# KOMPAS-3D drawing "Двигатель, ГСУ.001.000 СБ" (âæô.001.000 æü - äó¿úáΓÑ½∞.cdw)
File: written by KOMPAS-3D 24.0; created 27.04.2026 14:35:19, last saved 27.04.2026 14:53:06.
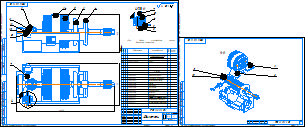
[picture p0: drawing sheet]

Document properties: Автор: User7; Форматы листов документа: A3, A2; Полное имя файла: ГСУ.001.000 СБ - Двигатель.a3d; Масса: 0.59734; Наименование: Двигатель; Количество листов документа: 2; Параметр неуказанной шероховатости: Ra 6,2

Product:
- Component [assembly]: Ротор  | designation ГСУ.001.100 СБ  | qty 1  | pos. 1  | Масса: 0.220757; source file: ГСУ.001.100 СБ - Ротор.a3d, ГСУ.001.100 СБ - Ротор.spw
- Component [detail]: Рама двигателя  | designation ГСУ.001.001  | qty 1  | pos. 4  | Масса: 0.218408; Автор: User7; source file: ГСУ.001.001 - Рама двигателя.m3d
- Component [detail]: Основание стартера  | designation ГСУ.001.002  | qty 2  | pos. 5  | Масса: 0.054294; Автор: User7; source file: ГСУ.001.002 - Основание стартера.m3d
- Component [detail]: Держатель щеток  | designation ГСУ.001.003  | qty 2  | pos. 6  | Масса: 0.006286; Автор: User7; source file: ГСУ.001.003 - Держатель щеток.m3d
- Component [detail]: Щетка  | designation ГСУ.001.004  | qty 2  | pos. 7  | Масса: 0.001131; Автор: User7; source file: ГСУ.001.004 - Щетка.m3d
- Component [detail]: Пластина  | designation ГСУ.001.005  | qty 2  | pos. 8  | Масса: 0.002713; Автор: User7; source file: ГСУ.001.005 - Пластина.m3d
- Component [detail]: Уплотнитель  | designation ГСУ.001.007  | qty 2  | pos. 10  | Масса: 0.000505; Автор: User7; source file: ГСУ.001.007 - Уплотнитель.m3d
- Component [detail]: Пружина  | designation ГСУ.001.008  | qty 2  | pos. 11  | Масса: 0.000147; Автор: User7; source file: ГСУ.001.008 - Пружина.m3d
- Component [detail]: Обмотка  | designation ГСУ.001.009  | qty 2  | pos. 12  | Масса: 0.009785; Автор: User7; source file: ГСУ.001.009 - Обмотка.m3d
- Component [detail]: Пластина держателя пружин  | designation ГСУ.001.011  | qty 2  | pos. 13  | Масса: 0.000005; Автор: User7; source file: ГСУ.001.011 - Пластина держателя пружин.m3d
- Component [detail]: Держатель стартера  | designation ГСУ.001.012  | qty 1  | pos. 14  | Масса: 0.003518; Автор: User7; source file: ГСУ.001.012 - Держатель стартера.m3d
- Component [detail]: Пластина держателя втулок ротора  | designation ГСУ.001.013  | qty 1  | pos. 15  | Масса: 0.000666; Автор: User7; source file: ГСУ.001.013 - Пластина держателя втулок ротора.m3d
- Component [detail]: Пластинка  | designation ГСУ.001.006  | qty 2  | pos. 9  | Масса: 0.002129; Автор: User7; source file: ГСУ.001.006 - Пластинка.m3d
- Part/product: Двигатель  | designation ГСУ.001.000 СБ
    Масса: 0.59734

Views: Выносной элемент 3, Выносной элемент А, Выносной элемент, Сечение проволоки, Сечение проволоки 2
Referenced files in C:\Users\User7\Desktop\Двигатель мясорубки\: ГСУ.001.000 СБ - Двигатель.a3d, ГСУ.001.100 СБ - Ротор.a3d, ГСУ.001.001 - Рама двигателя.m3d, ГСУ.001.002 - Основание стартера.m3d, ГСУ.001.003 - Держатель щеток.m3d, ГСУ.001.004 - Щетка.m3d, ГСУ.001.005 - Пластина.m3d, ГСУ.001.007 - Уплотнитель.m3d, ГСУ.001.008 - Пружина.m3d, ГСУ.001.009 - Обмотка.m3d, ГСУ.001.011 - Пластина держателя пружин.m3d, ГСУ.001.012 - Держатель стартера.m3d, ГСУ.001.013 - Пластина держателя втулок ротора.m3d, ГСУ.001.006 - Пластинка.m3d, ГСУ.001.000 СБ - Двигатель.cdw, ГСУ.001.101 - Звездочка.m3d, ГСУ.001.102 - Вал ротора.m3d, ГСУ.001.103 - Шестеренка.m3d, ГСУ.001.104 - Пропеллер.m3d, ГСУ.001.105 - Коллектор.m3d, ГСУ.001.106 - Шайба.m3d, ГСУ.001.107 - Втулка.m3d, ГСУ.001.108 - Пластина.m3d
Referenced files in C:\Program Files\ASCON\KOMPAS-3D v21\Libs\PARTLib\DATA\vault\Methods\Kompas\3D\: PLib_Nut_OST92_900.m3d
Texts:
  key
  prop
  position
  ГСУ.001.000 СБ
  Ra 6,2
  Ra 6,2 ( )
  Программные изделия  и базы данных
  Принадлежности
  Приспособления
  Упаковка
  ГСУ.001.100 СБ
  Ротор
  ГСУ.001.001
  Рама двигателя
  ГСУ.001.002
  Основание стартера
  ГСУ.001.003
  Держатель щеток
  ГСУ.001.004
  Щетка
  ГСУ.001.005
  Пластина
  ГСУ.001.007
  Уплотнитель
  ГСУ.001.008
  Пружина
  ГСУ.001.009
  Обмотка
  ГСУ.001.011
  Пластина держателя пружин
  ГСУ.001.012
  Держатель стартера
  ГСУ.001.013
  Пластина держателя втулок ротора
  ГСУ.001.006
  Пластинка
  Двигатель
  Звездочка
  ГСУ.001.101
  ГСУ.001.101 Звездочка
  Вал ротора
  ГСУ.001.102
  ГСУ.001.102 Вал ротора
  Шестеренка
  ГСУ.001.103
  ГСУ.001.103 Шестеренка
  Пропеллер
  ГСУ.001.104
  ГСУ.001.104 Пропеллер
  Коллектор
  ГСУ.001.105
  ГСУ.001.105 Коллектор
  Шайба
  ГСУ.001.106
  ГСУ.001.106 Шайба
  Втулка
  ГСУ.001.107
  ГСУ.001.107 Втулка
  ГСУ.001.108
  ГСУ.001.108 Пластина
  Гайка М4-6H ГОСТ 15523-70
  ГСУ.001.100 СБ Ротор
  ГСУ.001.001 Рама двигателя
  ГСУ.001.002 Основание стартера
  ГСУ.001.003 Держатель щеток
  ГСУ.001.004 Щетка
  ГСУ.001.005 Пластина
  ГСУ.001.007 Уплотнитель
  Спираль рабочих витков
  Спираль первого поджатого витка
  Спираль второго поджатого витка
  ГСУ.001.008 Пружина
  ГСУ.001.009 Обмотка
  ГСУ.001.011 Пластина держателя пружин
  ГСУ.001.012 Держатель стартера
  ГСУ.001.013 Пластина держателя втулок ротора
  ГСУ.001.006 Пластинка
  ГСУ.001.000 СБ Двигатель
Dimensions and other numbers on the sheet: 0; 2; 6; 3; 1; 4; 7; 11; 10; 5; 8; 12; 13; 14; 15; 9; 2:1; 0,6

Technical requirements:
  При сборке использовать смазку
  GOST Type AU
  ________________(уточнить у заказчика)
